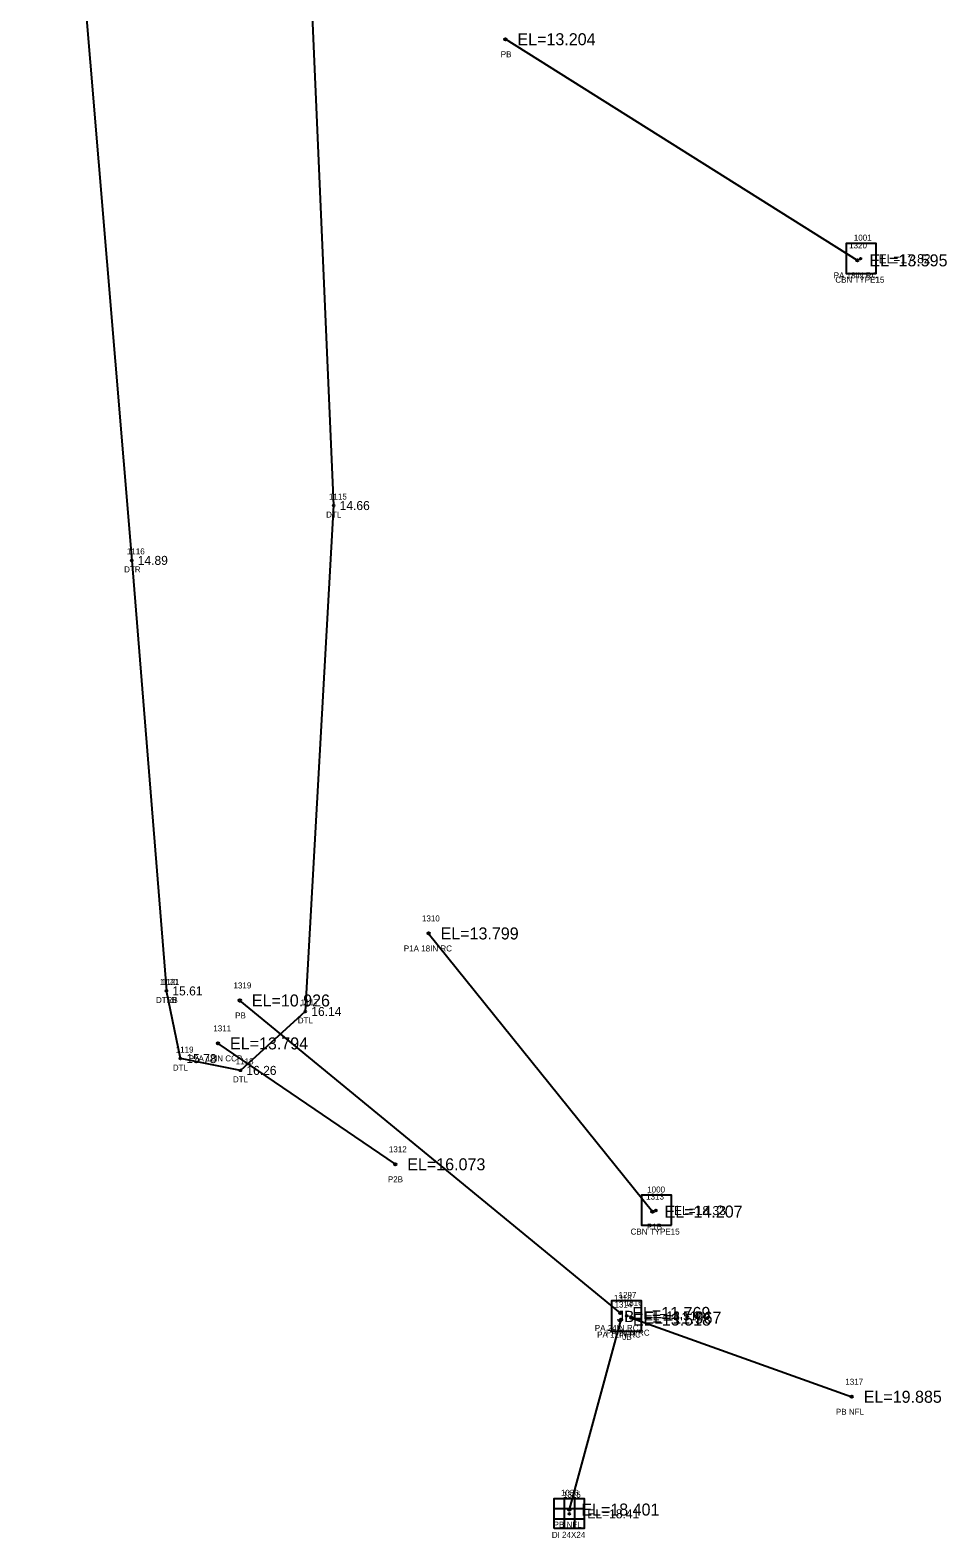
# Model space of a CAD drawing. Extents: x 2072307 to 2072993, y 127574 to 129736.
# Drawn here: x 2072393.7 to 2072546.4, y 127574.3 to 127825.4 of the extents above; entities that cross this region are included whole.
import ezdxf

# ---------------------------------------------------------------- set-up
doc = ezdxf.new("R2010")
doc.units = 0
for name, color, linetype in [('RD_EX_DR_Inlet', 7, 'Continuous'), ('RD_EX_DR_Inlet_txCode', 7, 'Continuous'), ('RD_EX_DR_Pipe', 7, 'Continuous'), ('RD_EX_DR_Pipe_txCode', 7, 'Continuous'), ('RD_EX_H2O', 7, 'Continuous'), ('RD_EX_H2O_txCode', 7, 'Continuous'), ('RD_EX_TX_DR_Inlet_ELEV', 7, 'Continuous'), ('RD_EX_TX_H2O_ELEV', 7, 'Continuous'), ('RD_SMD_Locator', 7, 'Continuous'), ('RD_TX_Pipe_ElevEX', 7, 'Continuous')]:
    doc.layers.add(name, color=color, linetype=linetype)

msp = doc.modelspace()

# ---------------------------------------------------------------- linework, layer by layer
at = {"layer": 'RD_EX_DR_Inlet'}
for p, q in [((2072534.65, 127784.87), (2072534.65, 127789.87)), ((2072500.55, 127626.37), (2072500.55, 127631.37)), ((2072495.57, 127608.76), (2072495.57, 127613.76)), ((2072482.69, 127580.88), (2072482.69, 127575.88)), ((2072484.39, 127580.88), (2072484.39, 127575.88)), ((2072480.99, 127579.18), (2072485.99, 127579.18)), ((2072480.99, 127577.48), (2072485.99, 127577.48))]:
    msp.add_line(p, q, dxfattribs=at)
for points in [[(2072534.65, 127784.87), (2072534.65, 127789.87), (2072529.65, 127789.87), (2072529.65, 127784.87)], [(2072500.55, 127626.37), (2072500.55, 127631.37), (2072495.55, 127631.37), (2072495.55, 127626.37)], [(2072495.57, 127608.76), (2072495.57, 127613.76), (2072490.57, 127613.76), (2072490.57, 127608.76)], [(2072480.99, 127575.88), (2072480.99, 127580.88), (2072485.99, 127580.88), (2072485.99, 127575.88)]]:
    msp.add_lwpolyline(points, close=True, dxfattribs=at)
at = {"layer": 'RD_EX_DR_Pipe'}
for p, q in [((2072531.52, 127787.04), (2072472.88, 127823.86)), ((2072460.07, 127674.96), (2072497.38, 127628.65)), ((2072492.01, 127611.77), (2072428.63, 127663.8)), ((2072424.99, 127656.65), (2072454.52, 127636.52)), ((2072492.11, 127610.67), (2072483.52, 127579.03)), ((2072493.85, 127610.98), (2072530.57, 127597.81))]:
    msp.add_line(p, q, dxfattribs=at)
at = {"layer": 'RD_EX_H2O'}
for points in [[(2072397.43, 128013.21), (2072408.15, 128037.05), (2072417.14, 128037.67), (2072426.18, 128028.89), (2072428.77, 128008.19), (2072436.1, 127925.95), (2072440.16, 127839.38), (2072444.26, 127746.21), (2072439.54, 127661.97), (2072428.72, 127652.16), (2072418.72, 127654.12), (2072416.39, 127665.39)], [(2072397.43, 128013.21), (2072393.69, 127930.01), (2072402.33, 127836.68), (2072410.62, 127737.08), (2072416.39, 127665.39)]]:
    msp.add_lwpolyline(points, dxfattribs=at)
at = {"layer": 'RD_SMD_Locator'}
for centre, radius in [((2072472.88, 127823.86), 0.2), ((2072531.52, 127787.04), 0.2), ((2072532.06, 127787.32), 0.15), ((2072444.26, 127746.21), 0.15), ((2072410.62, 127737.08), 0.15), ((2072460.07, 127674.96), 0.2), ((2072416.39, 127665.39), 0.15), ((2072416.39, 127665.39), 0.15), ((2072428.63, 127663.8), 0.2), ((2072439.54, 127661.97), 0.15), ((2072424.99, 127656.65), 0.2), ((2072418.72, 127654.12), 0.15), ((2072428.72, 127652.16), 0.15), ((2072454.52, 127636.52), 0.2), ((2072497.38, 127628.65), 0.2), ((2072497.96, 127628.82), 0.15), ((2072492.01, 127611.77), 0.2), ((2072492.11, 127610.67), 0.2), ((2072493.08, 127611.27), 0.15), ((2072493.85, 127610.98), 0.2), ((2072530.57, 127597.81), 0.2), ((2072483.52, 127579.03), 0.2), ((2072483.53, 127578.32), 0.15)]:
    msp.add_circle(centre, radius, dxfattribs=at)

# ---------------------------------------------------------------- texts
at = {"layer": 'RD_EX_DR_Inlet'}
msp.add_text('JB', height=1.875, dxfattribs=at).set_placement((2072491.42, 127610.25))
at = {"layer": 'RD_EX_DR_Inlet_txCode'}
for s, p in [('1001', (2072530.92, 127790.32)), ('CBN TYPE15', (2072527.84, 127783.32)), ('1000', (2072496.5, 127631.82)), ('CBN TYPE15', (2072493.73, 127624.82)), ('1297', (2072491.73, 127614.27)), ('JB', (2072492.36, 127607.27)), ('1036', (2072482.12, 127581.32)), ('DI 24X24', (2072480.61, 127574.32))]:
    msp.add_text(s, height=1, dxfattribs=at).set_placement(p)
at = {"layer": 'RD_EX_DR_Pipe_txCode'}
for s, p in [('PB', (2072472.1, 127820.86)), ('1320', (2072530.14, 127789.04)), ('PA 18IN RC', (2072527.57, 127784.04)), ('1310', (2072458.97, 127676.96)), ('P1A 18IN RC', (2072455.95, 127671.96)), ('1319', (2072427.57, 127665.8)), ('PB', (2072427.85, 127660.8)), ('1311', (2072424.21, 127658.65)), ('P2A 12IN CCP', (2072420.11, 127653.65)), ('1312', (2072453.46, 127638.52)), ('P2B', (2072453.29, 127633.52)), ('1313', (2072496.32, 127630.65)), ('P1B', (2072496.44, 127625.65)), ('1318', (2072490.94, 127613.77)), ('1314', (2072491.05, 127612.67)), ('1316', (2072492.77, 127612.98)), ('PA 24IN RC', (2072487.77, 127608.77)), ('PA 12IN RC', (2072488.16, 127607.67)), ('PA 24IN RC', (2072489.62, 127607.98)), ('1317', (2072529.5, 127599.81)), ('PB NFL', (2072527.94, 127594.81)), ('1315', (2072482.46, 127581.03)), ('PB NFL', (2072480.9, 127576.03))]:
    msp.add_text(s, height=1, dxfattribs=at).set_placement(p)
at = {"layer": 'RD_EX_H2O_txCode'}
for s, p in [('1115', (2072443.48, 127747.21)), ('DTL', (2072443.01, 127744.21)), ('1116', (2072409.81, 127738.08)), ('DTR', (2072409.35, 127735.08)), ('1120', (2072415.29, 127666.39)), ('1121', (2072415.61, 127666.39)), ('DTRB', (2072414.65, 127663.39)), ('DTLB', (2072414.67, 127663.39)), ('1117', (2072438.76, 127662.97)), ('DTL', (2072438.29, 127659.97)), ('1119', (2072417.94, 127655.12)), ('DTL', (2072417.47, 127652.12)), ('1118', (2072427.94, 127653.16)), ('DTL', (2072427.48, 127650.16))]:
    msp.add_text(s, height=1, dxfattribs=at).set_placement(p)
at = {"layer": 'RD_EX_TX_DR_Inlet_ELEV'}
for s, p in [('EL=17.82', (2072535.06, 127786.57)), ('EL=18.33', (2072500.96, 127628.07)), ('EL=18.510', (2072496.08, 127610.52)), ('EL=18.41', (2072486.53, 127577.57))]:
    msp.add_text(s, height=1.5, dxfattribs=at).set_placement(p)
at = {"layer": 'RD_EX_TX_H2O_ELEV'}
for s, p in [('14.66', (2072445.26, 127745.46)), ('14.89', (2072411.62, 127736.33)), ('15.61', (2072417.39, 127664.64)), ('15.61', (2072417.39, 127664.64)), ('16.14', (2072440.54, 127661.22)), ('15.78', (2072419.72, 127653.37)), ('16.26', (2072429.72, 127651.41))]:
    msp.add_text(s, height=1.5, dxfattribs=at).set_placement(p)
at = {"layer": 'RD_TX_Pipe_ElevEX'}
for s, p in [('EL=13.204', (2072474.88, 127822.86)), ('EL=13.595', (2072533.52, 127786.04)), ('EL=13.799', (2072462.07, 127673.96)), ('EL=10.926', (2072430.63, 127662.8)), ('EL=13.794', (2072426.99, 127655.65)), ('EL=16.073', (2072456.52, 127635.52)), ('EL=14.207', (2072499.38, 127627.65)), ('EL=11.769', (2072494.01, 127610.77)), ('EL=13.518', (2072494.11, 127609.67)), ('EL=11.967', (2072495.85, 127609.98)), ('EL=19.885', (2072532.57, 127596.81)), ('EL=18.401', (2072485.52, 127578.03))]:
    msp.add_text(s, height=2, dxfattribs=at).set_placement(p)

doc.saveas('drawing.dxf')
